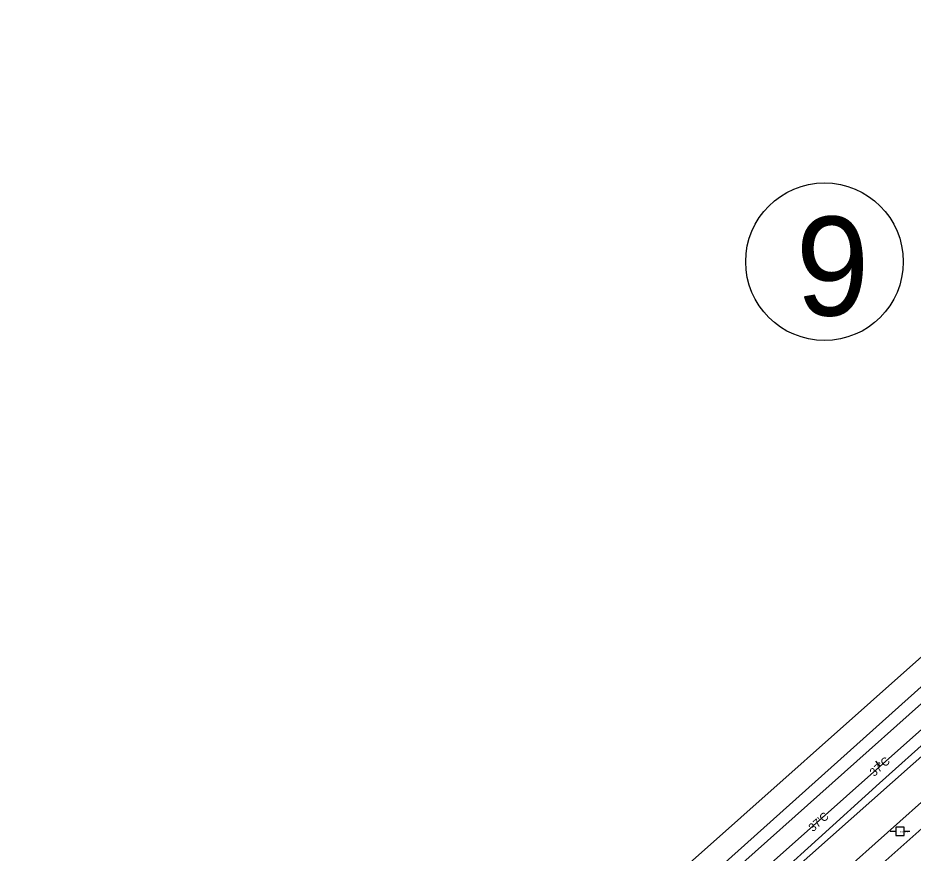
# Model space of a CAD drawing. Extents: x 50001 to 56005, y 49075 to 53926.
# Drawn here: x 52545 to 53088, y 51096 to 51602 of the extents above; entities that cross this region are included whole.
import ezdxf

# ---------------------------------------------------------------- set-up
doc = ezdxf.new("R2010")
doc.units = 0
for name, color, linetype in [('Level 1', 7, 'Continuous'), ('Level 11', 7, 'Continuous'), ('Level 12', 7, 'Continuous'), ('Level 18', 7, 'Continuous'), ('Level 19', 7, 'Continuous'), ('Level 20', 7, 'Continuous'), ('Level 25', 7, 'Continuous'), ('Level 3', 7, 'Continuous'), ('Level 59', 7, 'Continuous'), ('Level 9', 7, 'Continuous')]:
    doc.layers.add(name, color=color, linetype=linetype)

# ---------------------------------------------------------------- blocks, each defined once
blk = doc.blocks.new('PP')
at = {"layer": 'Level 9'}
for p, q in [((2.53, 2.45), (-2.47, 2.45)), ((-2.47, 2.45), (-2.47, -2.55)), ((2.53, -2.55), (2.53, 2.45)), ((-5.91, -0.11), (-2.44, -0.11)), ((-2.47, -2.55), (2.53, -2.55)), ((2.45, -0.11), (6.09, -0.11))]:
    blk.add_line(p, q, dxfattribs=at)

msp = doc.modelspace()

# ---------------------------------------------------------------- linework, layer by layer
at = {"layer": 'Level 1'}
for p, q in [((52544.81, 50683.3), (55534.58, 53340.86)), ((52714.15, 50773.62), (54181.77, 52078.16)), ((53068.13, 51148.47), (53065.47, 51151.46))]:
    msp.add_line(p, q, dxfattribs=at)
at = {"layer": 'Level 11'}
msp.add_line((52940.3, 51059.99), (53157.7, 51254.45), dxfattribs=at)
at = {"layer": 'Level 12'}
for p, q in [((52637.37, 50809.73), (53363.85, 51455.49)), ((53407.7, 51406.16), (52566.74, 50658.64))]:
    msp.add_line(p, q, dxfattribs=at)
at = {"layer": 'Level 18'}
for p, q in [((53067.78, 51138.09), (53104.93, 51171.56)), ((53030.67, 51104.58), (53067.78, 51138.09)), ((52993.51, 51071.13), (53030.67, 51104.58))]:
    msp.add_line(p, q, dxfattribs=at)
at = {"layer": 'Level 19'}
msp.add_line((52714.15, 50773.62), (54181.77, 52078.16), dxfattribs=at)
at = {"layer": 'Level 20'}
msp.add_line((52706.17, 50782.58), (53452.43, 51445.92), dxfattribs=at)
at = {"layer": 'Level 25'}
msp.add_circle((53034.33, 51454.43), 47.8, dxfattribs=at)
at = {"layer": 'Level 3'}
for p, q in [((52945.93, 51055.32), (53162.5, 51248.32)), ((52961.4, 51037.52), (53179.35, 51230.72))]:
    msp.add_line(p, q, dxfattribs=at)

# ---------------------------------------------------------------- block references
at = {"layer": 'Level 9'}
msp.add_blockref('PP', (53080.11, 51109.02), dxfattribs=at)

# ---------------------------------------------------------------- texts
at = {"layer": 'Level 18'}
for p in [(53064.46, 51141.83), (53027.34, 51108.32)]:
    msp.add_text("37'C", height=5, rotation=41.6334, dxfattribs=at).set_placement(p)
at = {"layer": 'Level 25'}
msp.add_text('9', height=60, dxfattribs=at).set_placement((53016.89, 51421.76))
at = {"layer": 'Level 59'}
msp.add_text('1332 PP', height=1, dxfattribs=at).set_placement((53080.11, 51108.02))

doc.saveas('drawing.dxf')
